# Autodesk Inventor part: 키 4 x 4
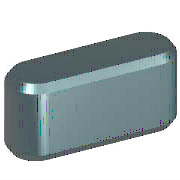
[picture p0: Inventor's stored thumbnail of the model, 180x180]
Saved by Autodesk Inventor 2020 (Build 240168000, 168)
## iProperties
Created: 2012-02
Part Number: 키 4 x 4
Material: 강철, 연강
Description: 키 및 해당 키홈
Document SubType Name: Modeling
Standard: KS B 1311
Designer: mduedu
Standards Organization: KS
Language: ko-KR
Size Designation: 4 x 4 x 18
Categories: <MemberInstance><Categories><Category DisplayName="샤프트 부품" InternalName="7f7aeb1f-a693-4053-b835-cee3144e0d98" Mnemonic="SHFT"><Category DisplayName="키" Interna
Density: 7.86 g/cm^3
Mass: 2.13606 g
Surface Area: 2.87354 cm^2
Volume: 0.271763 cm^3
Appearance: 노란색
IsCustomPart: 1
Author: mduedu
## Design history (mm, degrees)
workplane "Work Plane1"
workplane "Work Plane2"
sketch "스케치1"
  geometry: L1 (2, 2)-(16, 2); L2 (16, -2)-(2, -2); L3 (0, 9.4)-(0, -7.4) reference; L4 (-5, 0)-(30, 0) reference; L5 (18, 0)-(18, 7); A1 r 2 centre (2, 0) between (2, 2) and (2, -2); A2 r 2 centre (16, 0) between (16, -2) and (16, 2)
  constraints: 6 end point, 5 point on circle, 4 tangent, 3 point on line, 2 centre point, 1 horizontal, 1 parallel, 1 perpendicular
  dimensions: "d0" = 2 radius of A1 (= 0.5 x PB); "d13" = 2 radius of A2 (= 0.5 x PB); "d14" = 18 distance between parallel lines of L5 L3 (= NLG)
extrude "본체1" new body sketch "스케치1" taper "d3" = 0 deg; stored distance "d4" = 10
workplane "Work Plane3"
body "Solid1"
chamfer "모따기1" distance "d8" = 0.25 (= PHH); stored, may be unused: second distance "d9" = 0.25 (= PHH), angle "d15" = 45 deg
other parameters: "d1" = -2.5 (= -PNT), "d2" = 1.5 (= PH - PNT), "NLG" = 18 [user parameter; used in 3 equation terms], "PB" = 4 [user parameter; used in 2 equation terms], "PNT" = 2.5 [user parameter; used in 2 equation terms], "PH" = 4 [user parameter; used in 1 equation term], "PHH" = 0.25 [user parameter; used in 2 equation terms], "d10" = 0, "d16" = 0, "d17" = 0, "d18" = 0, "PLB2" = 18 (= NLG) [user parameter], "WDMAX" = 12 [user parameter], "PLB1" = 18 (= NLG) [user parameter], "RR" = 0.08 [user parameter], "PUEB" = 1.8 [user parameter]
